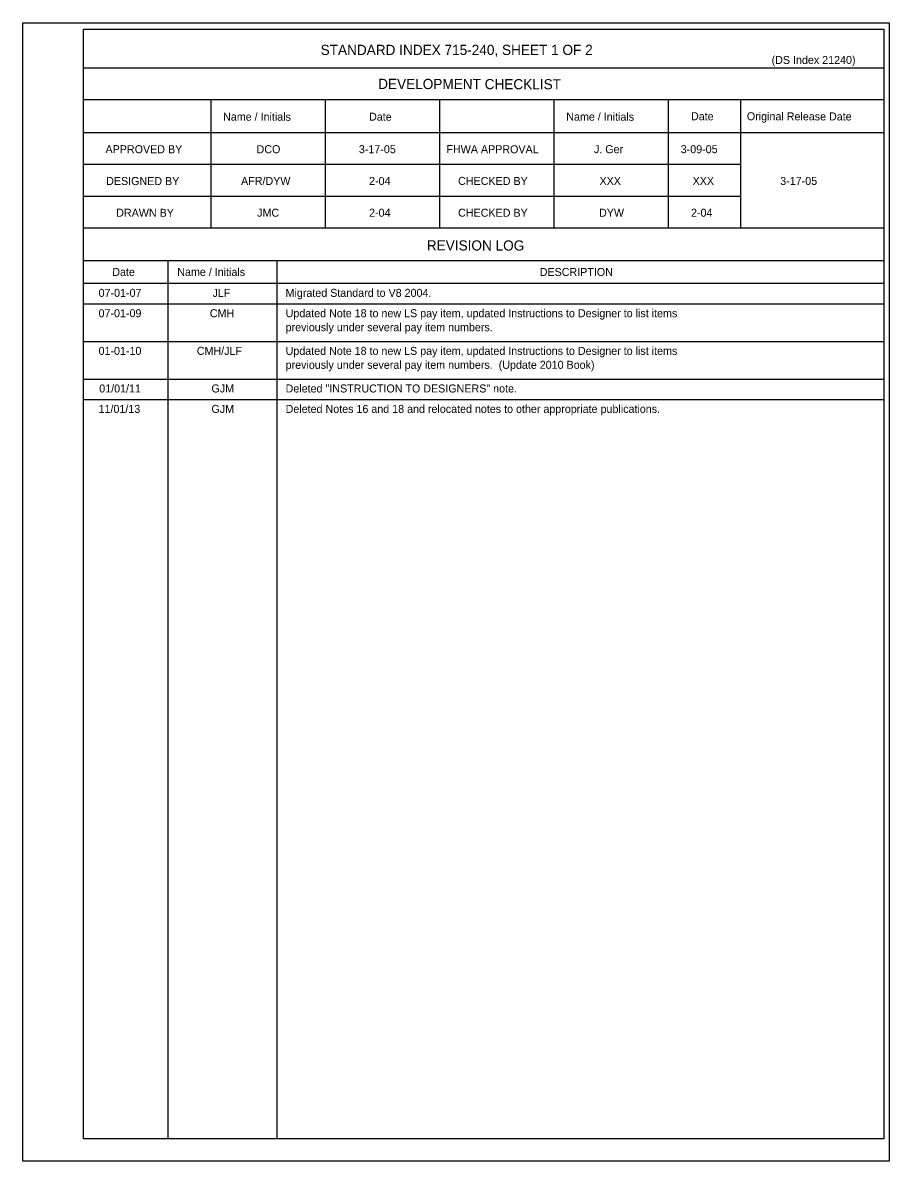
# Model space of a CAD drawing. Extents: x -0.2 to 16.2, y -0.2 to 21.2.
import ezdxf

# ---------------------------------------------------------------- set-up
doc = ezdxf.new("R2010")
doc.units = 0
for name, color, linetype in [('Border', 7, 'Continuous'), ('PlotBorder_dp', 7, 'Continuous'), ('TextStructures', 7, 'Continuous')]:
    doc.layers.add(name, color=color, linetype=linetype)

msp = doc.modelspace()

# ---------------------------------------------------------------- linework, layer by layer
at = {"layer": 'Border'}
for p, q in [((16.078, 20.393), (0.968, 20.393)), ((16.078, 19.793), (0.968, 19.793)), ((3.368, 19.793), (3.368, 17.372)), ((5.528, 19.793), (5.528, 17.372)), ((7.688, 19.793), (7.688, 17.372)), ((9.848, 19.793), (9.848, 17.372)), ((12.008, 19.793), (12.008, 17.372)), ((13.369, 19.793), (13.369, 17.372)), ((16.078, 19.172), (0.968, 19.172)), ((13.369, 18.572), (0.968, 18.572)), ((13.369, 17.972), (0.968, 17.972)), ((16.078, 17.372), (0.968, 17.372)), ((16.078, 16.751), (0.968, 16.751)), ((2.558, 16.751), (2.558, 0.171)), ((4.615, 16.751), (4.615, 0.171)), ((16.078, 16.328), (0.968, 16.328))]:
    msp.add_line(p, q, dxfattribs=at)
msp.add_lwpolyline([(0.968, 21.128), (16.078, 21.128), (16.078, 0.171), (0.968, 0.171)], close=True, dxfattribs=at)
at = {"layer": 'PlotBorder_dp'}
msp.add_line((-0.18, -0.25), (-0.18, -0.25), dxfattribs=at)
msp.add_lwpolyline([(-0.18, 21.25), (16.18, 21.25), (16.18, -0.25), (-0.18, -0.25)], close=True, dxfattribs=at)
at = {"layer": 'TextStructures'}
for p, q in [((0.968, 15.943), (16.078, 15.943)), ((0.968, 15.232), (16.078, 15.232)), ((0.968, 14.521), (16.078, 14.521)), ((0.968, 14.136), (16.078, 14.136))]:
    msp.add_line(p, q, dxfattribs=at)

# ---------------------------------------------------------------- texts
for s, height, p in [('STANDARD INDEX 715-240, SHEET 1 OF 2', 0.192, (5.444, 20.642)), ('(DS Index 21240)', 0.1512, (13.959, 20.472)), ('DCO', 0.1512, (4.235, 18.787)), ('3-17-05', 0.1512, (6.166, 18.787)), ('J. Ger', 0.1512, (10.605, 18.787)), ('3-09-05', 0.1512, (12.243, 18.787)), ('AFR/DYW', 0.1512, (3.942, 18.187)), ('2-04', 0.1512, (6.359, 18.187)), ('XXX', 0.1512, (10.71, 18.187)), ('XXX', 0.1512, (12.468, 18.187)), ('3-17-05', 0.1512, (14.122, 18.187)), ('JMC', 0.1512, (4.246, 17.587)), ('2-04', 0.1512, (6.359, 17.587)), ('DYW', 0.1512, (10.701, 17.587)), ('2-04', 0.1512, (12.437, 17.587)), ('DESCRIPTION', 0.1512, (9.581, 16.468)), ('07-01-07', 0.1512, (1.252, 16.074)), ('JLF', 0.1512, (3.403, 16.074)), ('Migrated Standard to V8 2004.', 0.1512, (4.782, 16.074)), ('07-01-09', 0.1512, (1.251, 15.689)), ('CMH', 0.1512, (3.352, 15.689)), ('Updated Note 18 to new LS pay item, updated Instructions to Designer to list items', 0.1512, (4.783, 15.689)), ('previously under several pay item numbers.', 0.1512, (4.783, 15.425)), ('01-01-10', 0.1512, (1.251, 14.978)), ('CMH/JLF', 0.1512, (3.106, 14.978)), ('Updated Note 18 to new LS pay item, updated Instructions to Designer to list items', 0.1512, (4.783, 14.978)), ('previously under several pay item numbers.  (Update 2010 Book)', 0.1512, (4.783, 14.715)), ('01/01/11', 0.1512, (1.264, 14.268)), ('GJM', 0.1512, (3.383, 14.268)), ('Deleted "INSTRUCTION TO DESIGNERS" note.', 0.1512, (4.783, 14.268)), ('11/01/13', 0.1512, (1.251, 13.882)), ('GJM', 0.1512, (3.383, 13.882)), ('Deleted Notes 16 and 18 and relocated notes to other appropriate publications.', 0.1512, (4.783, 13.882))]:
    msp.add_text(s, height=height, dxfattribs=at).set_placement(p)
for s, height, p in [('DEVELOPMENT CHECKLIST', 0.192, (6.53, 20)), ('Original Release Date', 0.1512, (13.492, 19.409)), ('Name / Initials', 0.1512, (3.602, 19.402)), ('Date', 0.1512, (6.358, 19.401)), ('Name / Initials', 0.1512, (10.082, 19.402)), ('Date', 0.1512, (12.437, 19.409)), ('APPROVED BY', 0.1512, (1.382, 18.788)), ('FHWA APPROVAL', 0.1512, (7.819, 18.788)), ('DESIGNED BY', 0.1512, (1.394, 18.187)), ('CHECKED BY', 0.1512, (8.04, 18.188)), ('DRAWN BY', 0.1512, (1.584, 17.587)), ('CHECKED BY', 0.1512, (8.04, 17.588)), ('REVISION LOG', 0.192, (7.449, 16.951)), ('Date', 0.1512, (1.51, 16.469)), ('Name / Initials', 0.1512, (2.737, 16.47))]:
    msp.add_text(s, height=height, rotation=359.8756, dxfattribs=at).set_placement(p)

doc.saveas('drawing.dxf')
